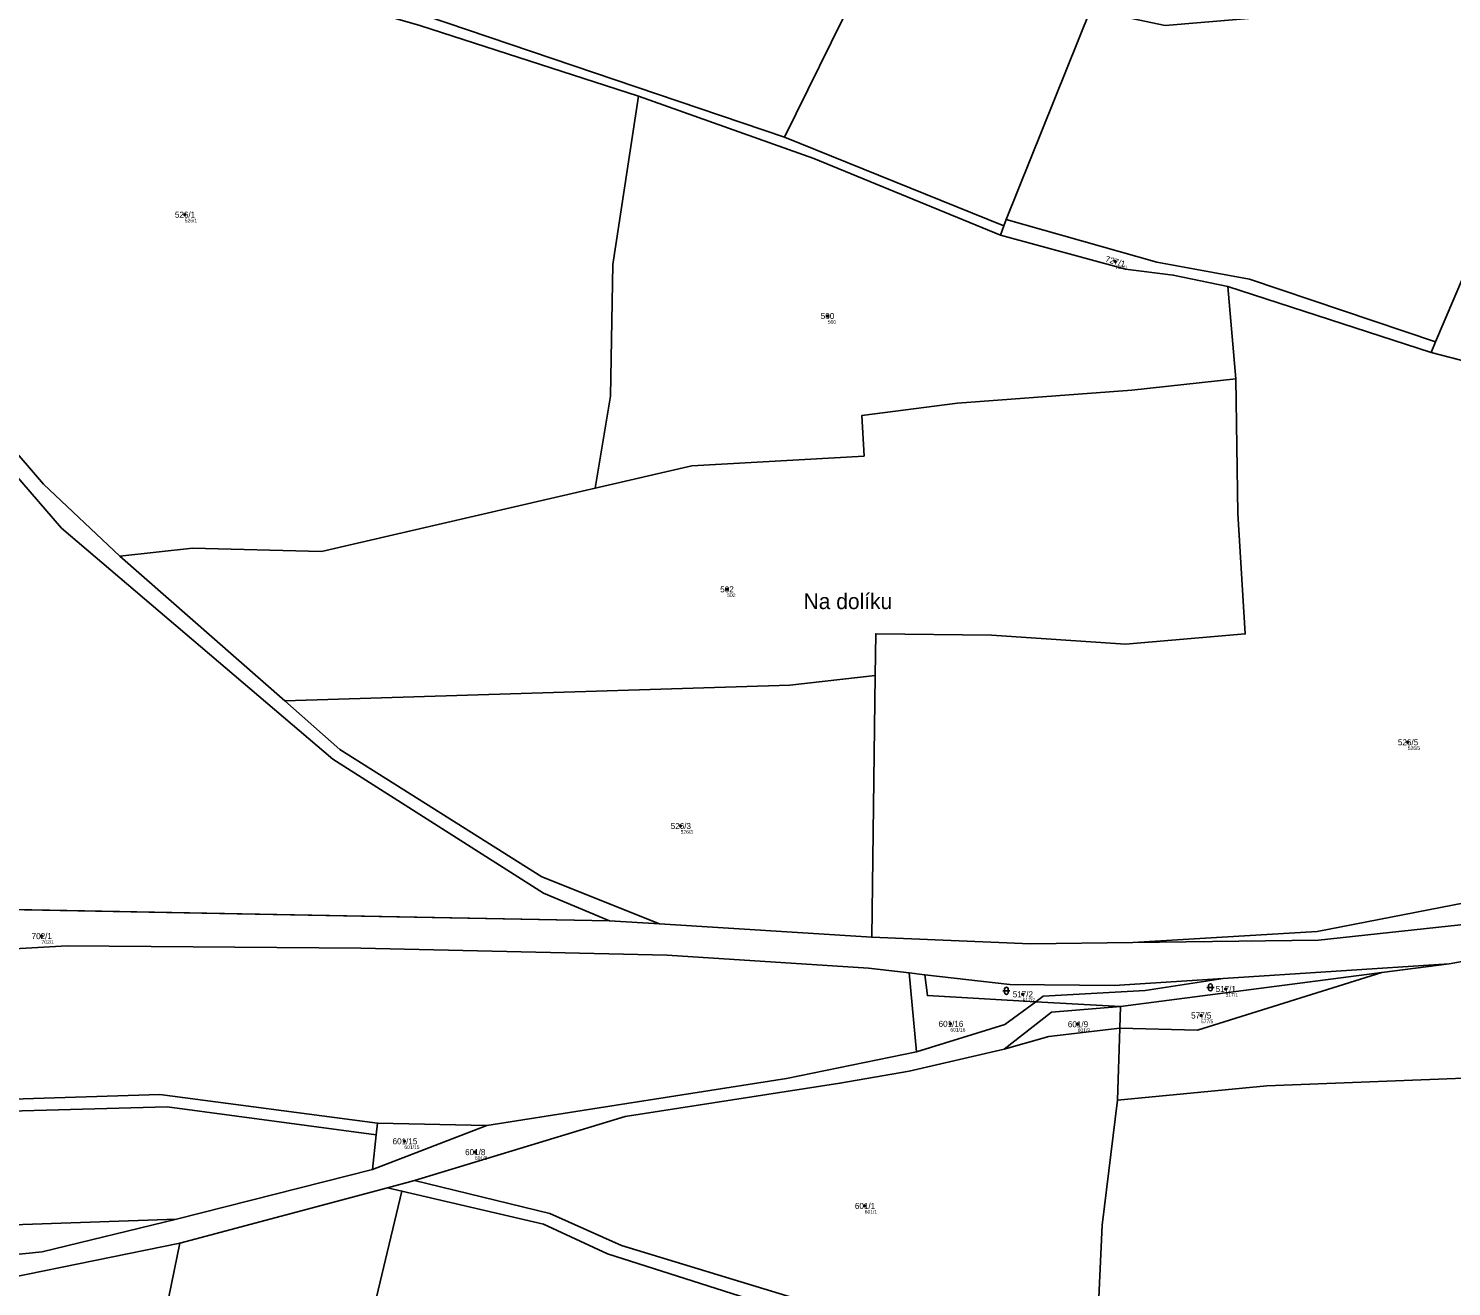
# Model space of a CAD drawing. Extents: x -767985 to -763816, y -1059600 to -1057360.
# Drawn here: x -764944.8 to -764545.8, y -1058857.3 to -1058504.4 of the extents above; entities that cross this region are included whole.
import ezdxf

# ---------------------------------------------------------------- set-up
doc = ezdxf.new("R2010")
doc.units = 0
for name, color, linetype in [('Definiční body', 7, 'Continuous'), ('Hranice parcel', 7, 'Continuous'), ('Parcelní čísla', 7, 'Continuous'), ('Polygon parcely', 7, 'Continuous'), ('Pop  PČ popisy', 7, 'Continuous'), ('Značky kultur', 7, 'Continuous')]:
    doc.layers.add(name, color=color, linetype=linetype)

msp = doc.modelspace()

# ---------------------------------------------------------------- linework, layer by layer
at = {"layer": 'Definiční body'}
for centre in [(-764900.99, -1058556.60994), (-764640.09, -1058569.72994), (-764720.67, -1058585.04994), (-764748.86, -1058661.68994), (-764558.03, -1058704.59994), (-764761.95, -1058728.09994), (-764941.17, -1058758.97994), (-764666.04, -1058775.28994), (-764609.13, -1058773.81994), (-764686.3, -1058783.58994), (-764650.58, -1058783.68994), (-764616.02, -1058781.24994), (-764839.41, -1058816.50994), (-764819.61, -1058819.56994), (-764710.3, -1058834.65994)]:
    msp.add_circle(centre, 0.25, dxfattribs=at)
at = {"layer": 'Hranice parcel'}
for p, q in [((-764833.57, -1058500.7), (-764732.85, -1058534.9)), ((-764647.02, -1058499.14), (-764670.62, -1058558)), ((-764732.85, -1058534.9), (-764671.28, -1058559.7)), ((-764671.28, -1058559.7), (-764672.25, -1058562.35)), ((-764671.28, -1058559.7), (-764670.62, -1058558)), ((-764606.24, -1058602.63), (-764608.47, -1058576.72)), ((-764551.51, -1058595.24), (-764608.47, -1058576.72)), ((-764550.23, -1058592.24), (-764551.51, -1058595.24)), ((-764491.96, -1058610.67), (-764551.51, -1058595.24)), ((-764872.98, -1058693.02), (-764919.19, -1058652.44)), ((-764708.33, -1058759.29), (-764707.37, -1058685.92)), ((-764781.91, -1058754.68), (-764955.94, -1058751.39)), ((-764767.89, -1058755.56), (-764781.91, -1058754.68)), ((-764708.33, -1058759.29), (-764767.89, -1058755.56)), ((-764609.76, -1058770.86), (-764546.46, -1058766.71)), ((-764565.32, -1058769.17), (-764546.46, -1058766.71)), ((-764695.78, -1058791.41), (-764697.82, -1058769.29)), ((-764697.82, -1058769.29), (-764693.43, -1058769.8)), ((-764638.6, -1058778.71), (-764565.32, -1058769.17)), ((-764662.35, -1058777.37), (-764638.6, -1058778.71)), ((-764638.6, -1058778.71), (-764638.77, -1058784.8)), ((-764639.47, -1058805.04), (-764638.77, -1058784.8)), ((-764816.31, -1058812.13), (-764848.35, -1058824.4)), ((-764847.3, -1058814.75), (-764846.94, -1058811.44)), ((-764846.94, -1058811.44), (-764816.31, -1058812.13)), ((-764848.35, -1058824.4), (-764847.3, -1058814.75)), ((-764903.36, -1058838.39), (-764848.35, -1058824.4)), ((-764844.13, -1058829.54), (-764836.55, -1058827.51)), ((-764902.35, -1058845.11), (-764844.13, -1058829.54)), ((-764840.08, -1058830.48), (-764844.13, -1058829.54)), ((-764950.02, -1058854.82), (-764902.35, -1058845.11))]:
    msp.add_line(p, q, dxfattribs=at)
for points in [[(-764550.23, -1058592.24), (-764542.36, -1058573.82), (-764542.36, -1058548.12), (-764515.44, -1058435.63), (-764497.4, -1058371.94), (-764487.98, -1058370.5)], [(-764700.52, -1058445.76), (-764705.85, -1058469.44), (-764716.5, -1058501.68), (-764732.85, -1058534.9)], [(-764773.8, -1058523.35), (-764835.06, -1058503.56), (-764905.63, -1058483.15), (-764951.07, -1058470.68), (-765014.89, -1058459.74)], [(-764785.87, -1058633.35), (-764781.57, -1058607.51), (-764780.96, -1058570.6), (-764773.8, -1058523.35)], [(-764672.25, -1058562.35), (-764724.57, -1058540.87), (-764773.8, -1058523.35)], [(-765088.12, -1058528.31), (-765081.94, -1058532.61), (-765045.52, -1058545.03), (-765034.9, -1058549.46), (-765002.23, -1058567.63), (-764980.9, -1058585.38), (-764940.58, -1058632.18), (-764919.19, -1058652.44)], [(-764670.62, -1058558), (-764628.42, -1058569.95), (-764602.37, -1058574.7), (-764550.23, -1058592.24)], [(-764608.47, -1058576.72), (-764623.82, -1058573.56), (-764637.15, -1058571.9), (-764672.25, -1058562.35)], [(-764785.87, -1058633.35), (-764758.83, -1058627.11), (-764710.48, -1058624.33), (-764711.11, -1058612.93), (-764684.28, -1058609.51), (-764635.42, -1058605.84), (-764606.24, -1058602.63)], [(-764707.37, -1058685.92), (-764707.22, -1058674.15), (-764674.77, -1058674.57), (-764637.19, -1058677.1), (-764603.63, -1058674.19), (-764605.65, -1058640.48), (-764606.24, -1058602.63)], [(-764950.78, -1058626.92), (-764935.52, -1058644.59), (-764859.47, -1058709.32), (-764800.43, -1058746.96), (-764781.91, -1058754.68)], [(-764919.19, -1058652.44), (-764898.82, -1058650.16), (-764862.62, -1058651.05), (-764785.87, -1058633.35)], [(-764872.98, -1058693.02), (-764731.31, -1058688.6), (-764707.37, -1058685.92)], [(-764767.89, -1058755.56), (-764800.88, -1058742.32), (-764857.49, -1058706.63), (-764872.98, -1058693.02)], [(-764490.46, -1058750.12), (-764528.23, -1058746.91), (-764583.48, -1058757.7), (-764635.1, -1058760.77)], [(-764490.46, -1058750.12), (-764583.05, -1058760.07), (-764635.1, -1058760.77)], [(-764635.1, -1058760.77), (-764663.81, -1058761.15), (-764708.33, -1058759.29)], [(-765160.68, -1058782.9), (-765094.28, -1058770.01), (-764995.8, -1058762.98), (-764952.07, -1058762.78), (-764934.01, -1058761.72), (-764851.66, -1058762.39), (-764765.72, -1058764.32), (-764709.3, -1058767.95), (-764697.82, -1058769.29)], [(-764546.46, -1058766.71), (-764531.81, -1058764.14), (-764504.93, -1058762.17)], [(-764693.43, -1058769.8), (-764692.73, -1058775.66), (-764662.35, -1058777.37)], [(-764693.43, -1058769.8), (-764669.6, -1058772.58), (-764640.39, -1058772.87), (-764609.76, -1058770.86)], [(-764609.76, -1058770.86), (-764631.69, -1058774.28), (-764660.24, -1058775.82), (-764662.35, -1058777.37)], [(-764565.32, -1058769.17), (-764617.02, -1058785.39), (-764638.77, -1058784.8)], [(-764662.35, -1058777.37), (-764671.03, -1058783.77), (-764695.78, -1058791.41)], [(-764671.21, -1058790.67), (-764657.97, -1058780.28), (-764638.6, -1058778.71)], [(-764638.77, -1058784.8), (-764658.72, -1058787.1), (-764671.21, -1058790.67)], [(-764671.21, -1058790.67), (-764697.82, -1058796.84), (-764717.29, -1058800.24), (-764777.48, -1058809.58), (-764836.55, -1058827.51)], [(-764695.78, -1058791.41), (-764732.29, -1058798.88), (-764784.76, -1058807.17), (-764816.31, -1058812.13)], [(-764846.94, -1058811.44), (-764907.96, -1058803.39), (-764949.27, -1058804.68), (-765027.24, -1058797.71), (-765028.79, -1058808.04), (-765083.01, -1058806.49), (-765105.09, -1058806.88), (-765134.7, -1058809.39)], [(-764639.47, -1058805.04), (-764597.53, -1058801), (-764535.04, -1058798.52), (-764502.82, -1058803.24), (-764502.32, -1058839.71), (-764470.72, -1058846.01)], [(-765134.06, -1058811.56), (-765103.08, -1058810.24), (-765082.76, -1058809.86), (-765027.55, -1058810.63), (-765025.43, -1058800.9), (-764949.98, -1058808.04), (-764905.94, -1058806.88), (-764847.3, -1058814.75)], [(-764647.54, -1058894.05), (-764644.74, -1058862.37), (-764643.69, -1058840.03), (-764639.47, -1058805.04)], [(-764836.55, -1058827.51), (-764798.66, -1058836.76), (-764778.51, -1058845.73), (-764727.85, -1058861.2), (-764659.73, -1058887.38), (-764647.54, -1058894.05)], [(-764840.08, -1058830.48), (-764854.92, -1058892.3), (-764859.06, -1058918.7)], [(-764725.9, -1058866.15), (-764782.44, -1058848.06), (-764800.39, -1058839.74), (-764840.08, -1058830.48)], [(-765108.31, -1058833.83), (-765060.52, -1058841.2), (-764990.71, -1058843.9), (-764946.41, -1058839.89), (-764903.36, -1058838.39)], [(-764903.36, -1058838.39), (-764941, -1058847.56), (-764950.17, -1058848.48)], [(-764902.35, -1058845.11), (-764915.58, -1058909.39), (-764919.02, -1058945.35)]]:
    msp.add_lwpolyline(points, dxfattribs=at)
at = {"layer": 'Polygon parcely'}
for points in [[(-764559.35, -1058228.38), (-764557.36, -1058263.13), (-764550.17, -1058302.02), (-764548.73, -1058350.41), (-764549.59, -1058390.35), (-764565.12, -1058458.49), (-764571.17, -1058476.06), (-764583.84, -1058499.96), (-764626.07, -1058503.55), (-764647.02, -1058499.14), (-764670.62, -1058558), (-764628.42, -1058569.95), (-764602.37, -1058574.7), (-764550.23, -1058592.24), (-764542.36, -1058573.82), (-764542.36, -1058548.12), (-764515.44, -1058435.63), (-764497.4, -1058371.94), (-764487.98, -1058370.5), (-764486.4, -1058358), (-764485.87, -1058342.5), (-764501.57, -1058261.88), (-764501.99, -1058233.31), (-764556.13, -1058229.11)], [(-764693.81, -1058415.93), (-764700.52, -1058445.76), (-764705.85, -1058469.44), (-764716.5, -1058501.68), (-764732.85, -1058534.9), (-764671.28, -1058559.7), (-764670.62, -1058558), (-764647.02, -1058499.14), (-764640.91, -1058480.83), (-764644.04, -1058466.25), (-764639.27, -1058435.88), (-764617.59, -1058373.1), (-764610.96, -1058338.83), (-764609.95, -1058307.65), (-764614.36, -1058257.2), (-764629.33, -1058256.93), (-764643.66, -1058278.56), (-764651.78, -1058300.96), (-764664.07, -1058311.08)], [(-764487.98, -1058370.5), (-764497.4, -1058371.94), (-764515.44, -1058435.63), (-764542.36, -1058548.12), (-764542.36, -1058573.82), (-764550.23, -1058592.24), (-764551.51, -1058595.24), (-764491.96, -1058610.67), (-764465.68, -1058592.43), (-764456.15, -1058583.87), (-764444.28, -1058554.04), (-764431.06, -1058489.86), (-764421.12, -1058422.48), (-764411.48, -1058397.71), (-764406.02, -1058374.74), (-764406.14, -1058356.86)], [(-764823.2, -1058486.89), (-764833.57, -1058500.7), (-764732.85, -1058534.9), (-764716.5, -1058501.68), (-764705.85, -1058469.44), (-764700.52, -1058445.76), (-764753.92, -1058434.52), (-764754.95, -1058439.36), (-764800.74, -1058424.15), (-764808, -1058447.48), (-764815.08, -1058468.05)], [(-765017.69, -1058485.9), (-765019.99, -1058533.39), (-765045.15, -1058533.82), (-765063.53, -1058532.73), (-765088.12, -1058528.31), (-765081.94, -1058532.61), (-765045.52, -1058545.03), (-765034.9, -1058549.46), (-765002.23, -1058567.63), (-764980.9, -1058585.38), (-764940.58, -1058632.18), (-764919.19, -1058652.44), (-764898.82, -1058650.16), (-764862.62, -1058651.05), (-764785.87, -1058633.35), (-764781.57, -1058607.51), (-764780.96, -1058570.6), (-764773.8, -1058523.35), (-764835.06, -1058503.56), (-764905.63, -1058483.15), (-764951.07, -1058470.68), (-765014.89, -1058459.74)], [(-764623.82, -1058573.56), (-764637.15, -1058571.9), (-764672.25, -1058562.35), (-764724.57, -1058540.87), (-764773.8, -1058523.35), (-764780.96, -1058570.6), (-764781.57, -1058607.51), (-764785.87, -1058633.35), (-764758.83, -1058627.11), (-764710.48, -1058624.33), (-764711.11, -1058612.93), (-764684.28, -1058609.51), (-764635.42, -1058605.84), (-764606.24, -1058602.63), (-764608.47, -1058576.72)], [(-764671.28, -1058559.7), (-764672.25, -1058562.35), (-764637.15, -1058571.9), (-764623.82, -1058573.56), (-764608.47, -1058576.72), (-764551.51, -1058595.24), (-764550.23, -1058592.24), (-764602.37, -1058574.7), (-764628.42, -1058569.95), (-764670.62, -1058558)], [(-764674.77, -1058674.57), (-764637.19, -1058677.1), (-764603.63, -1058674.19), (-764605.65, -1058640.48), (-764606.24, -1058602.63), (-764635.42, -1058605.84), (-764684.28, -1058609.51), (-764711.11, -1058612.93), (-764710.48, -1058624.33), (-764758.83, -1058627.11), (-764785.87, -1058633.35), (-764862.62, -1058651.05), (-764898.82, -1058650.16), (-764919.19, -1058652.44), (-764872.98, -1058693.02), (-764731.31, -1058688.6), (-764707.37, -1058685.92), (-764707.22, -1058674.15)], [(-764984.74, -1058705.36), (-764952.23, -1058706.01), (-764955.94, -1058751.39), (-764781.91, -1058754.68), (-764800.43, -1058746.96), (-764859.47, -1058709.32), (-764935.52, -1058644.59), (-764950.78, -1058626.92), (-764972.33, -1058628.14), (-765005.37, -1058625.95), (-765062.5, -1058614.27), (-765069.1, -1058653.02), (-765050.21, -1058655.81), (-765031.16, -1058656.88), (-765014.2, -1058658.87), (-765020.05, -1058702.24)], [(-764708.33, -1058759.29), (-764707.37, -1058685.92), (-764731.31, -1058688.6), (-764872.98, -1058693.02), (-764857.49, -1058706.63), (-764800.88, -1058742.32), (-764767.89, -1058755.56)], [(-764528.23, -1058746.91), (-764583.48, -1058757.7), (-764635.1, -1058760.77), (-764583.05, -1058760.07), (-764490.46, -1058750.12)], [(-764816.31, -1058812.13), (-764784.76, -1058807.17), (-764732.29, -1058798.88), (-764695.78, -1058791.41), (-764697.82, -1058769.29), (-764709.3, -1058767.95), (-764765.72, -1058764.32), (-764851.66, -1058762.39), (-764934.01, -1058761.72), (-764952.07, -1058762.78), (-764995.8, -1058762.98), (-765094.28, -1058770.01), (-765160.68, -1058782.9), (-765161.67, -1058786.86), (-765138.91, -1058787.03), (-765134.7, -1058809.39), (-765105.09, -1058806.88), (-765083.01, -1058806.49), (-765028.79, -1058808.04), (-765027.24, -1058797.71), (-764949.27, -1058804.68), (-764907.96, -1058803.39), (-764846.94, -1058811.44)], [(-764565.32, -1058769.17), (-764617.02, -1058785.39), (-764638.77, -1058784.8), (-764639.47, -1058805.04), (-764597.53, -1058801), (-764535.04, -1058798.52), (-764502.82, -1058803.24), (-764502.32, -1058839.71), (-764470.72, -1058846.01), (-764380.09, -1058868.72), (-764371.09, -1058775.68), (-764435.08, -1058763.17), (-764465.63, -1058763.92), (-764504.93, -1058762.17), (-764531.81, -1058764.14), (-764546.46, -1058766.71)], [(-764565.32, -1058769.17), (-764546.46, -1058766.71), (-764609.76, -1058770.86), (-764631.69, -1058774.28), (-764660.24, -1058775.82), (-764662.35, -1058777.37), (-764638.6, -1058778.71)], [(-764693.43, -1058769.8), (-764697.82, -1058769.29), (-764695.78, -1058791.41), (-764671.03, -1058783.77), (-764662.35, -1058777.37), (-764692.73, -1058775.66)], [(-764692.73, -1058775.66), (-764662.35, -1058777.37), (-764660.24, -1058775.82), (-764631.69, -1058774.28), (-764609.76, -1058770.86), (-764640.39, -1058772.87), (-764669.6, -1058772.58), (-764693.43, -1058769.8)], [(-764638.6, -1058778.71), (-764638.77, -1058784.8), (-764617.02, -1058785.39), (-764565.32, -1058769.17)], [(-764671.21, -1058790.67), (-764657.97, -1058780.28), (-764638.6, -1058778.71), (-764662.35, -1058777.37), (-764671.03, -1058783.77), (-764695.78, -1058791.41), (-764732.29, -1058798.88), (-764784.76, -1058807.17), (-764816.31, -1058812.13), (-764848.35, -1058824.4), (-764903.36, -1058838.39), (-764941, -1058847.56), (-764950.17, -1058848.48), (-764950.02, -1058854.82), (-764902.35, -1058845.11), (-764844.13, -1058829.54), (-764836.55, -1058827.51), (-764777.48, -1058809.58), (-764717.29, -1058800.24), (-764697.82, -1058796.84)], [(-764671.21, -1058790.67), (-764658.72, -1058787.1), (-764638.77, -1058784.8), (-764638.6, -1058778.71), (-764657.97, -1058780.28)], [(-764643.69, -1058840.03), (-764639.47, -1058805.04), (-764638.77, -1058784.8), (-764658.72, -1058787.1), (-764671.21, -1058790.67), (-764697.82, -1058796.84), (-764717.29, -1058800.24), (-764777.48, -1058809.58), (-764836.55, -1058827.51), (-764798.66, -1058836.76), (-764778.51, -1058845.73), (-764727.85, -1058861.2), (-764659.73, -1058887.38), (-764647.54, -1058894.05), (-764644.74, -1058862.37)], [(-765082.76, -1058809.86), (-765027.55, -1058810.63), (-765025.43, -1058800.9), (-764949.98, -1058808.04), (-764905.94, -1058806.88), (-764847.3, -1058814.75), (-764846.94, -1058811.44), (-764907.96, -1058803.39), (-764949.27, -1058804.68), (-765027.24, -1058797.71), (-765028.79, -1058808.04), (-765083.01, -1058806.49), (-765105.09, -1058806.88), (-765134.7, -1058809.39), (-765134.06, -1058811.56), (-765103.08, -1058810.24)], [(-764554.5, -1058931.66), (-764533.08, -1058945.22), (-764510.68, -1058952.79), (-764506.78, -1058934.04), (-764501.82, -1058900.74), (-764495.74, -1058876.16), (-764474.53, -1058878.21), (-764475.06, -1058865.2), (-764470.72, -1058846.01), (-764502.32, -1058839.71), (-764502.82, -1058803.24), (-764535.04, -1058798.52), (-764597.53, -1058801), (-764639.47, -1058805.04), (-764643.69, -1058840.03), (-764644.74, -1058862.37), (-764647.54, -1058894.05), (-764602.1, -1058910.08)], [(-764848.35, -1058824.4), (-764847.3, -1058814.75), (-764905.94, -1058806.88), (-764949.98, -1058808.04), (-765025.43, -1058800.9), (-765027.55, -1058810.63), (-765082.76, -1058809.86), (-765103.08, -1058810.24), (-765134.06, -1058811.56), (-765133.31, -1058814.06), (-765120.25, -1058830.25), (-765108.31, -1058833.83), (-765060.52, -1058841.2), (-764990.71, -1058843.9), (-764946.41, -1058839.89), (-764903.36, -1058838.39)], [(-764846.94, -1058811.44), (-764847.3, -1058814.75), (-764848.35, -1058824.4), (-764816.31, -1058812.13)], [(-764647.54, -1058894.05), (-764659.73, -1058887.38), (-764727.85, -1058861.2), (-764778.51, -1058845.73), (-764798.66, -1058836.76), (-764836.55, -1058827.51), (-764844.13, -1058829.54), (-764840.08, -1058830.48), (-764800.39, -1058839.74), (-764782.44, -1058848.06), (-764725.9, -1058866.15), (-764656.11, -1058892.9), (-764647.72, -1058896.12)], [(-764915.58, -1058909.39), (-764919.02, -1058945.35), (-764860.51, -1058958.1), (-764859.28, -1058922.59), (-764859.06, -1058918.7), (-764854.92, -1058892.3), (-764840.08, -1058830.48), (-764844.13, -1058829.54), (-764902.35, -1058845.11)], [(-764782.44, -1058848.06), (-764800.39, -1058839.74), (-764840.08, -1058830.48), (-764854.92, -1058892.3), (-764859.06, -1058918.7), (-764777.27, -1058922.19), (-764735.1, -1058926.49), (-764734.33, -1058914), (-764725.9, -1058866.15)], [(-765108.31, -1058833.83), (-765062.34, -1058847.6), (-765026.7, -1058850.9), (-764950.17, -1058848.48), (-764941, -1058847.56), (-764903.36, -1058838.39), (-764946.41, -1058839.89), (-764990.71, -1058843.9), (-765060.52, -1058841.2)], [(-765083.53, -1058937.7), (-765059.36, -1058946.68), (-765043.5, -1058961.97), (-765022.31, -1058952.23), (-764990.51, -1058955.99), (-764973.74, -1058954.16), (-764951.2, -1058953.97), (-764919.02, -1058945.35), (-764915.58, -1058909.39), (-764902.35, -1058845.11), (-764950.02, -1058854.82), (-764967.87, -1058863.09), (-764991.88, -1058866.15), (-765022.41, -1058866.43), (-765032.36, -1058908.82), (-765035.35, -1058910.02), (-765088.93, -1058925.33), (-765087.3, -1058928.67)]]:
    msp.add_lwpolyline(points, close=True, dxfattribs=at)
for points in [[(-764835.06, -1058503.56), (-764773.8, -1058523.35), (-764724.57, -1058540.87), (-764672.25, -1058562.35), (-764671.28, -1058559.7), (-764732.85, -1058534.9), (-764833.57, -1058500.7)], [(-764491.96, -1058610.67), (-764551.51, -1058595.24), (-764608.47, -1058576.72), (-764606.24, -1058602.63), (-764605.65, -1058640.48), (-764603.63, -1058674.19), (-764637.19, -1058677.1), (-764674.77, -1058674.57), (-764707.22, -1058674.15), (-764707.37, -1058685.92), (-764708.33, -1058759.29), (-764663.81, -1058761.15), (-764635.1, -1058760.77), (-764583.48, -1058757.7), (-764528.23, -1058746.91)], [(-764950.78, -1058626.92), (-764935.52, -1058644.59), (-764859.47, -1058709.32), (-764800.43, -1058746.96), (-764781.91, -1058754.68), (-764767.89, -1058755.56), (-764800.88, -1058742.32), (-764857.49, -1058706.63), (-764872.98, -1058693.02), (-764919.19, -1058652.44), (-764940.58, -1058632.18), (-764980.9, -1058585.38)], [(-764490.46, -1058750.12), (-764583.05, -1058760.07), (-764635.1, -1058760.77), (-764663.81, -1058761.15), (-764708.33, -1058759.29), (-764767.89, -1058755.56), (-764781.91, -1058754.68), (-764955.94, -1058751.39), (-765007.64, -1058753.52), (-765076.84, -1058759.95), (-765103.47, -1058762.24), (-765159.9, -1058771.97), (-765192.46, -1058777.22), (-765241.73, -1058781.07), (-765298.27, -1058782.43), (-765303.25, -1058781.83), (-765332.75, -1058781.44), (-765339.02, -1058780.16)], [(-765342.8, -1058790.42), (-765310.21, -1058793.25), (-765298.4, -1058791.82), (-765212.77, -1058787.77), (-765189.09, -1058785.56), (-765160.68, -1058782.9), (-765094.28, -1058770.01), (-764995.8, -1058762.98), (-764952.07, -1058762.78), (-764934.01, -1058761.72), (-764851.66, -1058762.39), (-764765.72, -1058764.32), (-764709.3, -1058767.95), (-764697.82, -1058769.29), (-764693.43, -1058769.8), (-764669.6, -1058772.58), (-764640.39, -1058772.87), (-764609.76, -1058770.86), (-764546.46, -1058766.71), (-764531.81, -1058764.14)]]:
    msp.add_lwpolyline(points, dxfattribs=at)
at = {"layer": 'Značky kultur'}
for p, q in [((-764671.581, -1058774.311), (-764669.579, -1058774.311)), ((-764671.081, -1058773.811), (-764671.081, -1058774.812)), ((-764670.079, -1058774.812), (-764670.079, -1058773.811)), ((-764614.371, -1058773.351), (-764612.369, -1058773.351)), ((-764613.871, -1058772.851), (-764613.871, -1058773.852)), ((-764612.869, -1058773.852), (-764612.869, -1058772.851))]:
    msp.add_line(p, q, dxfattribs=at)
for centre, start, end in [((-764613.37, -1058772.8509), 0, 180), ((-764670.58, -1058773.8109), 0, 180), ((-764670.58, -1058774.8109), 180, 359.9878861), ((-764613.37, -1058773.8509), 180, 359.9878861)]:
    msp.add_arc(centre, 0.5, start, end, dxfattribs=at)

# ---------------------------------------------------------------- texts
at = {"layer": 'Definiční body'}
for s, p in [('526/1', (-764900.99, -1058558.766)), ('727/1', (-764640.09, -1058571.886)), ('500', (-764720.67, -1058587.206)), ('502', (-764748.86, -1058663.846)), ('526/5', (-764558.03, -1058706.756)), ('526/3', (-764761.95, -1058730.256)), ('702/1', (-764941.17, -1058761.136)), ('517/2', (-764666.04, -1058777.446)), ('517/1', (-764609.13, -1058775.976)), ('577/5', (-764616.02, -1058783.406)), ('601/16', (-764686.3, -1058785.746)), ('601/9', (-764650.58, -1058785.846)), ('601/15', (-764839.41, -1058818.666)), ('601/8', (-764819.61, -1058821.726)), ('601/1', (-764710.3, -1058836.816))]:
    msp.add_text(s, height=0.999996, dxfattribs=at).set_placement(p)
at = {"layer": 'Parcelní čísla'}
for s, p in [('526/1', (-764903.763, -1058557.46)), ('500', (-764722.644, -1058585.9)), ('502', (-764750.834, -1058662.54)), ('526/5', (-764560.803, -1058705.45)), ('526/3', (-764764.723, -1058728.95)), ('702/1', (-764943.943, -1058759.83)), ('517/2', (-764668.813, -1058776.14)), ('517/1', (-764611.903, -1058774.67)), ('577/5', (-764618.793, -1058782.1)), ('601/16', (-764689.605, -1058784.44)), ('601/9', (-764653.353, -1058784.54)), ('601/15', (-764842.715, -1058817.36)), ('601/8', (-764822.383, -1058820.42)), ('601/1', (-764713.073, -1058835.51))]:
    msp.add_text(s, height=1.699998, dxfattribs=at).set_placement(p)
msp.add_text('727/1', height=1.699998, rotation=344, dxfattribs=at).set_placement((-764642.99, -1058569.782))
at = {"layer": 'Pop  PČ popisy'}
msp.add_text('Na dolíku', height=4.399998, dxfattribs=at).set_placement((-764727.46, -1058667.26))

doc.saveas('drawing.dxf')
